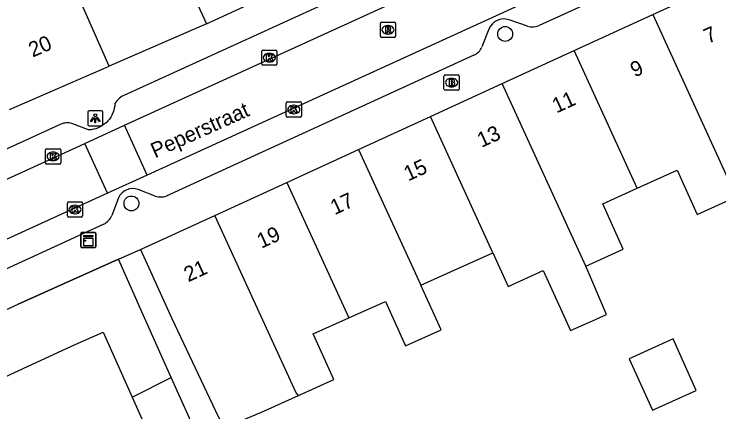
# Model space of a CAD drawing. Extents: x 159888 to 160757, y 384031 to 384746.
# Drawn here: x 160447.04 to 160493.49, y 384427.74 to 384453.93 of the extents above; entities that cross this region are included whole.
import ezdxf

# ---------------------------------------------------------------- set-up
doc = ezdxf.new("R2010")
doc.units = 0
for name, color, linetype in [('IMGEO_Boom', 7, 'Continuous'), ('IMGEO_Brandkraan', 7, 'Continuous'), ('IMGEO_Kast', 7, 'Continuous'), ('IMGEO_Kolk', 7, 'Continuous'), ('IMGEO_Lichtpunt', 7, 'Continuous'), ('IMGEO_Muur', 7, 'Continuous'), ('IMGEO_Openbare_ruimte_label', 7, 'Continuous'), ('IMGEO_Pand', 7, 'Continuous'), ('IMGEO_Pand_nummerreeks', 7, 'Continuous'), ('IMGEO_Rijbaan_lokaal_open', 7, 'Continuous'), ('IMGEO_Rioolput', 7, 'Continuous'), ('IMGEO_Voetpad_open', 7, 'Continuous')]:
    doc.layers.add(name, color=color, linetype=linetype)

msp = doc.modelspace()

# ---------------------------------------------------------------- linework, layer by layer
at = {"layer": 'IMGEO_Boom'}
for centre in [(160479.404, 384452.629), (160454.78, 384441.462)]:
    msp.add_circle(centre, 0.489, dxfattribs=at)
at = {"layer": 'IMGEO_Brandkraan'}
for p, q in [((160475.373, 384448.998), (160475.373, 384449.85)), ((160475.448, 384449.924), (160476.3, 384449.924)), ((160475.861, 384449.704), (160475.886, 384449.704)), ((160476.374, 384449.85), (160476.374, 384448.998)), ((160475.884, 384449.144), (160475.859, 384449.144)), ((160476.3, 384448.924), (160475.448, 384448.924))]:
    msp.add_line(p, q, dxfattribs=at)
for points in [[(160475.373, 384448.998), (160475.373, 384449.85)], [(160475.448, 384449.924), (160476.3, 384449.924)], [(160475.721, 384449.624), (160475.721, 384449.224), (160475.934, 384449.224)], [(160475.952, 384449.624), (160475.721, 384449.624)], [(160475.9, 384449.543), (160475.846, 384449.543), (160475.846, 384449.467)], [(160476.374, 384449.85), (160476.374, 384448.998)], [(160475.846, 384449.467), (160475.899, 384449.467)], [(160475.908, 384449.391), (160475.846, 384449.391), (160475.846, 384449.31)], [(160475.846, 384449.31), (160475.908, 384449.31)], [(160476.3, 384448.924), (160475.448, 384448.924)]]:
    msp.add_lwpolyline(points, dxfattribs=at)
for centre, radius, start, end in [((160475.45, 384449.848), 0.0765, 91.552, 178.448), ((160475.45, 384449.848), 0.0765, 91.552, 178.448), ((160475.901, 384449.505), 0.0379, 267.8285, 90.9355), ((160475.956, 384449.479), 0.145, 59.4692, 91.5367), ((160475.981, 384449.526), 0.0922, 285.5137, 58.1501), ((160476.298, 384449.848), 0.0765, 1.552, 88.448), ((160476.298, 384449.848), 0.0765, 1.552, 88.448), ((160475.909, 384449.35), 0.0404, 269.8759, 90.5077), ((160475.94, 384449.475), 0.251, 268.6676, 293.5347), ((160475.986, 384449.334), 0.105, 301.3115, 78.989), ((160475.45, 384449), 0.0765, 181.552, 268.448), ((160475.45, 384449), 0.0765, 181.552, 268.448), ((160476.298, 384449), 0.0765, 271.552, 358.448), ((160476.298, 384449), 0.0765, 271.552, 358.448)]:
    msp.add_arc(centre, radius, start, end, dxfattribs=at)
for centre, major_axis, ratio, start_param, end_param in [((160475.86, 384449.424), (-0.387, 0.002), 0.722429, 4.712389, 7.853982), ((160475.885, 384449.424), (-0.39, 0.002), 0.717154, 1.570796, 4.712389)]:
    msp.add_ellipse(centre, major_axis=major_axis, ratio=ratio, start_param=start_param, end_param=end_param, dxfattribs=at)
at = {"layer": 'IMGEO_Kast'}
for p, q in [((160451.436, 384438.628), (160451.436, 384439.469)), ((160451.436, 384439.469), (160451.436, 384438.628)), ((160451.511, 384439.553), (160452.352, 384439.553)), ((160452.352, 384439.553), (160451.511, 384439.553)), ((160452.436, 384439.478), (160452.436, 384438.637)), ((160452.436, 384438.637), (160452.436, 384439.478)), ((160452.361, 384438.553), (160451.52, 384438.553)), ((160451.52, 384438.553), (160452.361, 384438.553))]:
    msp.add_line(p, q, dxfattribs=at)
for points in [[(160451.631, 384439.343), (160452.231, 384439.343), (160452.231, 384439.258), (160451.631, 384439.258), (160451.631, 384439.343)], [(160451.631, 384439.168), (160452.231, 384439.168), (160452.231, 384438.679), (160451.631, 384438.679), (160451.631, 384439.168)]]:
    msp.add_lwpolyline(points, dxfattribs=at)
msp.add_circle((160451.715, 384439.017), 0.0377, dxfattribs=at)
for centre, start, end in [((160451.514, 384439.475), 92.4484, 184.2845), ((160451.514, 384439.475), 92.4484, 184.2845), ((160452.358, 384439.475), 2.4484, 94.2845), ((160452.358, 384439.475), 2.4484, 94.2845), ((160451.514, 384438.631), 182.4484, 274.2845), ((160451.514, 384438.631), 182.4484, 274.2845), ((160452.358, 384438.631), 272.4484, 4.2845), ((160452.358, 384438.631), 272.4484, 4.2845)]:
    msp.add_arc(centre, 0.0779, start, end, dxfattribs=at)
at = {"layer": 'IMGEO_Kolk'}
for p, q in [((160463.362, 384450.641), (160463.362, 384451.493)), ((160463.437, 384451.567), (160464.289, 384451.567)), ((160464.363, 384451.493), (160464.363, 384450.641)), ((160463.85, 384451.347), (160463.875, 384451.347)), ((160464.289, 384450.567), (160463.437, 384450.567)), ((160463.873, 384450.787), (160463.848, 384450.787)), ((160465.049, 384448.15), (160465.901, 384448.15)), ((160464.974, 384447.224), (160464.974, 384448.076)), ((160465.462, 384447.93), (160465.487, 384447.93)), ((160465.975, 384448.076), (160465.975, 384447.224)), ((160465.485, 384447.37), (160465.46, 384447.37)), ((160465.901, 384447.15), (160465.049, 384447.15)), ((160449.114, 384444.136), (160449.114, 384444.988)), ((160449.189, 384445.062), (160450.041, 384445.062)), ((160450.115, 384444.988), (160450.115, 384444.136)), ((160449.602, 384444.842), (160449.627, 384444.842)), ((160450.041, 384444.062), (160449.189, 384444.062)), ((160449.625, 384444.282), (160449.6, 384444.282)), ((160450.556, 384440.64), (160450.556, 384441.492)), ((160450.631, 384441.566), (160451.483, 384441.566)), ((160451.044, 384441.346), (160451.069, 384441.346)), ((160451.557, 384441.492), (160451.557, 384440.64)), ((160451.067, 384440.786), (160451.042, 384440.786)), ((160451.483, 384440.566), (160450.631, 384440.566))]:
    msp.add_line(p, q, dxfattribs=at)
for points in [[(160463.362, 384450.641), (160463.362, 384451.493)], [(160463.437, 384451.567), (160464.289, 384451.567)], [(160464.363, 384451.493), (160464.363, 384450.641)], [(160463.683, 384451.267), (160463.806, 384451.267), (160463.806, 384451.116), (160463.936, 384451.267), (160464.1, 384451.267), (160463.954, 384451.116), (160464.107, 384450.867), (160463.955, 384450.867), (160463.87, 384451.031), (160463.806, 384450.964), (160463.806, 384450.867), (160463.683, 384450.867), (160463.683, 384451.267)], [(160464.289, 384450.567), (160463.437, 384450.567)], [(160465.049, 384448.15), (160465.901, 384448.15)], [(160464.974, 384447.224), (160464.974, 384448.076)], [(160465.295, 384447.85), (160465.418, 384447.85), (160465.418, 384447.699), (160465.548, 384447.85), (160465.712, 384447.85), (160465.566, 384447.699), (160465.719, 384447.45), (160465.567, 384447.45), (160465.482, 384447.614), (160465.418, 384447.547), (160465.418, 384447.45), (160465.295, 384447.45), (160465.295, 384447.85)], [(160465.975, 384448.076), (160465.975, 384447.224)], [(160465.901, 384447.15), (160465.049, 384447.15)], [(160449.114, 384444.136), (160449.114, 384444.988)], [(160449.189, 384445.062), (160450.041, 384445.062)], [(160450.115, 384444.988), (160450.115, 384444.136)], [(160449.435, 384444.762), (160449.558, 384444.762), (160449.558, 384444.611), (160449.688, 384444.762), (160449.852, 384444.762), (160449.706, 384444.611), (160449.859, 384444.362), (160449.707, 384444.362), (160449.622, 384444.526), (160449.558, 384444.459), (160449.558, 384444.362), (160449.435, 384444.362), (160449.435, 384444.762)], [(160450.041, 384444.062), (160449.189, 384444.062)], [(160450.556, 384440.64), (160450.556, 384441.492)], [(160450.631, 384441.566), (160451.483, 384441.566)], [(160450.877, 384441.266), (160451, 384441.266), (160451, 384441.115), (160451.13, 384441.266), (160451.294, 384441.266), (160451.148, 384441.115), (160451.301, 384440.866), (160451.149, 384440.866), (160451.064, 384441.03), (160451, 384440.963), (160451, 384440.866), (160450.877, 384440.866), (160450.877, 384441.266)], [(160451.557, 384441.492), (160451.557, 384440.64)], [(160451.483, 384440.566), (160450.631, 384440.566)]]:
    msp.add_lwpolyline(points, dxfattribs=at)
for centre, start, end in [((160463.439, 384451.491), 91.552, 178.448), ((160463.439, 384451.491), 91.552, 178.448), ((160464.287, 384451.491), 1.552, 88.448), ((160464.287, 384451.491), 1.552, 88.448), ((160463.439, 384450.643), 181.552, 268.448), ((160463.439, 384450.643), 181.552, 268.448), ((160464.287, 384450.643), 271.552, 358.448), ((160464.287, 384450.643), 271.552, 358.448), ((160465.051, 384448.074), 91.552, 178.448), ((160465.051, 384448.074), 91.552, 178.448), ((160465.899, 384448.074), 1.552, 88.448), ((160465.899, 384448.074), 1.552, 88.448), ((160465.051, 384447.226), 181.552, 268.448), ((160465.051, 384447.226), 181.552, 268.448), ((160465.899, 384447.226), 271.552, 358.448), ((160465.899, 384447.226), 271.552, 358.448), ((160449.191, 384444.986), 91.552, 178.448), ((160449.191, 384444.986), 91.552, 178.448), ((160450.039, 384444.986), 1.552, 88.448), ((160450.039, 384444.986), 1.552, 88.448), ((160449.191, 384444.138), 181.552, 268.448), ((160449.191, 384444.138), 181.552, 268.448), ((160450.039, 384444.138), 271.552, 358.448), ((160450.039, 384444.138), 271.552, 358.448), ((160450.633, 384441.49), 91.552, 178.448), ((160450.633, 384441.49), 91.552, 178.448), ((160451.481, 384441.49), 1.552, 88.448), ((160451.481, 384441.49), 1.552, 88.448), ((160450.633, 384440.642), 181.552, 268.448), ((160450.633, 384440.642), 181.552, 268.448), ((160451.481, 384440.642), 271.552, 358.448), ((160451.481, 384440.642), 271.552, 358.448)]:
    msp.add_arc(centre, 0.0765, start, end, dxfattribs=at)
for centre, major_axis, ratio, start_param, end_param in [((160463.849, 384451.067), (-0.387, 0.002), 0.722429, 4.712389, 7.853982), ((160463.874, 384451.067), (-0.39, 0.002), 0.717154, 1.570796, 4.712389), ((160465.461, 384447.65), (-0.387, 0.002), 0.722429, 4.712389, 7.853982), ((160465.486, 384447.65), (-0.39, 0.002), 0.717154, 1.570796, 4.712389), ((160449.601, 384444.562), (-0.387, 0.002), 0.722429, 4.712389, 7.853982), ((160449.626, 384444.562), (-0.39, 0.002), 0.717154, 1.570796, 4.712389), ((160451.043, 384441.066), (-0.387, 0.002), 0.722429, 4.712389, 7.853982), ((160451.068, 384441.066), (-0.39, 0.002), 0.717154, 1.570796, 4.712389)]:
    msp.add_ellipse(centre, major_axis=major_axis, ratio=ratio, start_param=start_param, end_param=end_param, dxfattribs=at)
at = {"layer": 'IMGEO_Lichtpunt'}
for p, q in [((160451.894, 384447.474), (160451.894, 384446.667)), ((160451.894, 384447.474), (160451.894, 384446.667)), ((160452.796, 384447.569), (160451.988, 384447.569)), ((160452.796, 384447.569), (160451.988, 384447.569)), ((160452.89, 384446.667), (160452.89, 384447.474)), ((160452.89, 384446.667), (160452.89, 384447.474)), ((160451.988, 384446.573), (160452.796, 384446.573)), ((160451.988, 384446.573), (160452.796, 384446.573))]:
    msp.add_line(p, q, dxfattribs=at)
for points in [[(160452.268, 384447.138), (160452.307, 384447.11), (160452.119, 384446.848), (160452.081, 384446.875), (160452.268, 384447.138)], [(160452.37, 384447.09), (160452.417, 384447.09), (160452.417, 384446.768), (160452.37, 384446.768), (160452.37, 384447.09)], [(160452.48, 384447.11), (160452.518, 384447.137), (160452.705, 384446.875), (160452.666, 384446.847), (160452.48, 384447.11)]]:
    msp.add_lwpolyline(points, dxfattribs=at)
msp.add_circle((160452.393, 384447.272), 0.0994, dxfattribs=at)
for centre, start, end in [((160451.988, 384447.474), 90, 180), ((160451.988, 384447.474), 90, 180), ((160452.796, 384447.474), 0, 90), ((160452.796, 384447.474), 0, 90), ((160451.988, 384446.667), 180, 270), ((160451.988, 384446.667), 180, 270), ((160452.796, 384446.667), 270, 0), ((160452.796, 384446.667), 270, 360)]:
    msp.add_arc(centre, 0.0946, start, end, dxfattribs=at)
at = {"layer": 'IMGEO_Muur'}
msp.add_lwpolyline([(160453.931, 384437.792), (160447.309, 384434.839)], dxfattribs=at)
at = {"layer": 'IMGEO_Pand'}
for points in [[(160454.088, 384465.492), (160459.727, 384453.302)], [(160453.303, 384450.51), (160450.11, 384457.763)], [(160489.138, 384453.904), (160494.567, 384456.391)], [(160459.727, 384453.302), (160465.459, 384455.957)], [(160483.95, 384451.527), (160489.138, 384453.904)], [(160489.138, 384453.904), (160494.635, 384441.9)], [(160459.727, 384453.302), (160453.303, 384450.51)], [(160479.215, 384449.358), (160483.95, 384451.527)], [(160488.096, 384442.47), (160483.95, 384451.527)], [(160446.743, 384447.659), (160453.303, 384450.51)], [(160474.48, 384447.188), (160479.215, 384449.358)], [(160484.717, 384437.341), (160479.215, 384449.358)], [(160469.745, 384445.019), (160474.48, 384447.188)], [(160478.586, 384438.22), (160474.48, 384447.188)], [(160465.01, 384442.85), (160469.745, 384445.019)], [(160469.745, 384445.019), (160473.839, 384436.077)], [(160488.096, 384442.47), (160490.734, 384443.661), (160492.055, 384440.736), (160494.635, 384441.9)], [(160460.276, 384440.681), (160465.01, 384442.85)], [(160465.01, 384442.85), (160469.101, 384433.926)], [(160484.717, 384437.341), (160487.184, 384438.455), (160485.833, 384441.449), (160488.096, 384442.47)], [(160455.382, 384438.439), (160460.276, 384440.681)], [(160465.784, 384428.812), (160465.625, 384428.999), (160460.276, 384440.681)], [(160455.382, 384438.439), (160457.439, 384433.882), (160460.493, 384427.436), (160460.892, 384426.684)], [(160473.839, 384436.077), (160476.242, 384437.162), (160478.586, 384438.22)], [(160478.586, 384438.22), (160479.61, 384435.984), (160481.915, 384437.039), (160482.255, 384436.285), (160483.699, 384433.086), (160484.959, 384433.655), (160486.076, 384434.16), (160484.717, 384437.341)], [(160433.519, 384424.249), (160433.504, 384425.741), (160439.345, 384431.166), (160447.309, 384434.839), (160453.93, 384437.792)], [(160457.405, 384430.008), (160455.56, 384434.139), (160453.93, 384437.792)], [(160469.101, 384433.926), (160471.51, 384435.014), (160472.834, 384432.082), (160475.183, 384433.142), (160473.839, 384436.077)], [(160465.784, 384428.812), (160468.114, 384429.864), (160466.757, 384432.868), (160469.101, 384433.926)], [(160442.579, 384427.165), (160444.334, 384428.795), (160444.591, 384429.182), (160448.254, 384430.872), (160451.074, 384432.172), (160452.913, 384432.978), (160454.815, 384428.715)], [(160489.106, 384427.843), (160491.997, 384429.146), (160490.466, 384432.541), (160487.575, 384431.238), (160489.106, 384427.843)], [(160454.815, 384428.715), (160457.405, 384430.008)], [(160459.209, 384425.964), (160457.405, 384430.008)], [(160454.815, 384428.715), (160457.121, 384423.549), (160459.411, 384425.511), (160459.209, 384425.964)], [(160460.892, 384426.684), (160463.343, 384427.71), (160465.784, 384428.812)]]:
    msp.add_lwpolyline(points, dxfattribs=at)
at = {"layer": 'IMGEO_Rijbaan_lokaal_open'}
for points in [[(160454.317, 384446.611), (160493.72, 384464.601)], [(160495.213, 384461.332), (160455.807, 384443.337)], [(160451.715, 384445.423), (160454.317, 384446.611)], [(160455.807, 384443.337), (160454.317, 384446.611)], [(160427.031, 384432.494), (160428.207, 384433.465), (160429.629, 384434.635), (160431.79, 384436.112), (160434.074, 384437.389), (160447.578, 384443.534), (160451.715, 384445.423)], [(160453.206, 384442.149), (160451.715, 384445.423)], [(160455.807, 384443.337), (160453.206, 384442.149)], [(160453.206, 384442.149), (160435.156, 384433.906), (160430.297, 384430.523), (160430.292, 384430.519)]]:
    msp.add_lwpolyline(points, dxfattribs=at)
at = {"layer": 'IMGEO_Rioolput'}
for p, q in [((160471.182, 384452.476), (160471.182, 384453.328)), ((160471.257, 384453.402), (160472.109, 384453.402)), ((160472.183, 384453.328), (160472.183, 384452.476)), ((160471.67, 384453.182), (160471.695, 384453.182)), ((160472.109, 384452.402), (160471.257, 384452.402)), ((160471.693, 384452.622), (160471.668, 384452.622))]:
    msp.add_line(p, q, dxfattribs=at)
for points in [[(160471.182, 384452.476), (160471.182, 384453.328)], [(160471.257, 384453.402), (160472.109, 384453.402)], [(160472.183, 384453.328), (160472.183, 384452.476)], [(160471.771, 384453.1), (160471.519, 384453.102), (160471.519, 384452.702)], [(160471.519, 384452.702), (160471.643, 384452.702), (160471.643, 384452.864), (160471.654, 384452.864)], [(160471.697, 384453.021), (160471.643, 384453.021), (160471.643, 384452.94)], [(160471.643, 384452.94), (160471.695, 384452.94)], [(160471.701, 384452.835), (160471.772, 384452.702), (160471.912, 384452.702), (160471.847, 384452.828)], [(160472.109, 384452.402), (160471.257, 384452.402)]]:
    msp.add_lwpolyline(points, dxfattribs=at)
for centre, radius, start, end in [((160471.259, 384453.326), 0.0765, 91.552, 178.448), ((160471.259, 384453.326), 0.0765, 91.552, 178.448), ((160472.107, 384453.326), 0.0765, 1.552, 88.448), ((160472.107, 384453.326), 0.0765, 1.552, 88.448), ((160471.653, 384452.811), 0.0533, 26.0293, 88.6989), ((160471.679, 384453.129), 0.19, 274.7715, 282.9687), ((160471.703, 384452.925), 0.0964, 77.0061, 93.1865), ((160471.717, 384452.982), 0.0378, 276.6634, 79.6772), ((160471.77, 384452.99), 0.109, 350.3612, 89.416), ((160471.768, 384452.99), 0.112, 277.5842, 350.9817), ((160471.752, 384452.775), 0.108, 29.5134, 73.7905), ((160471.259, 384452.478), 0.0765, 181.552, 268.448), ((160471.259, 384452.478), 0.0765, 181.552, 268.448), ((160472.107, 384452.478), 0.0765, 271.552, 358.448), ((160472.107, 384452.478), 0.0765, 271.552, 358.448)]:
    msp.add_arc(centre, radius, start, end, dxfattribs=at)
for centre, major_axis, ratio, start_param, end_param in [((160471.669, 384452.902), (-0.387, 0.002), 0.722429, 4.712389, 7.853982), ((160471.694, 384452.902), (-0.39, 0.002), 0.717154, 1.570796, 4.712389)]:
    msp.add_ellipse(centre, major_axis=major_axis, ratio=ratio, start_param=start_param, end_param=end_param, dxfattribs=at)
at = {"layer": 'IMGEO_Voetpad_open'}
for points in [[(160495.357, 384459.421), (160481.641, 384453.176)], [(160474.316, 384457.729), (160454.273, 384448.571), (160454.171, 384448.52), (160454.074, 384448.46), (160453.982, 384448.391), (160453.897, 384448.314), (160453.819, 384448.231), (160453.75, 384448.14), (160453.684, 384448.037), (160453.674, 384447.896), (160453.65, 384447.739), (160453.611, 384447.584), (160453.559, 384447.434), (160453.493, 384447.288), (160453.415, 384447.15), (160453.325, 384447.018), (160453.224, 384446.896), (160453.111, 384446.782), (160452.99, 384446.68), (160452.859, 384446.588), (160452.721, 384446.509), (160452.576, 384446.442), (160452.426, 384446.389), (160452.272, 384446.349), (160452.115, 384446.323), (160451.956, 384446.311), (160450.857, 384446.732), (160450.765, 384446.755), (160450.672, 384446.769), (160450.578, 384446.775), (160450.483, 384446.773), (160450.39, 384446.762), (160450.297, 384446.743), (160450.207, 384446.715), (160450.119, 384446.68), (160450.082, 384446.662), (160433.681, 384439.158)], [(160480.886, 384453.138), (160479.659, 384453.561)], [(160478.336, 384452.953), (160477.874, 384451.768)], [(160477.338, 384451.227), (160457.075, 384441.954)], [(160456.348, 384441.951), (160455.22, 384442.392)], [(160453.922, 384441.83), (160453.492, 384440.662)], [(160452.963, 384440.089), (160437.486, 384433.018)], [(160453.93, 384437.792), (160455.382, 384438.439)]]:
    msp.add_lwpolyline(points, dxfattribs=at)
for centre, radius, start, end in [((160479.326, 384452.542), 1.072, 71.8906, 157.4728), ((160481.213, 384454.155), 1.068, 252.1644, 293.5983), ((160476.942, 384452.155), 1.009, 293.0966, 337.4354), ((160454.882, 384441.393), 1.054, 71.2908, 155.5319), ((160456.707, 384442.978), 1.088, 250.7241, 289.7488), ((160452.15, 384441.37), 1.517, 302.3959, 332.177)]:
    msp.add_arc(centre, radius, start, end, dxfattribs=at)

# ---------------------------------------------------------------- texts
at = {"layer": 'IMGEO_Openbare_ruimte_label'}
msp.add_text('Peperstraat', height=1, rotation=24.2068, dxfattribs=at).set_placement((160456.33, 384444.434))
at = {"layer": 'IMGEO_Pand_nummerreeks'}
for s, rotation, p in [('7', 24.6143, (160492.775, 384451.963)), ('20', 23.4913, (160448.264, 384451.067)), ('9', 24.6142, (160487.938, 384449.747)), ('11', 24.6142, (160482.787, 384447.387)), ('13', 24.6143, (160477.846, 384445.123)), ('15', 24.6143, (160473.009, 384442.907)), ('17', 24.6143, (160468.172, 384440.691)), ('19', 24.6142, (160463.335, 384438.476)), ('21', 24.6143, (160458.518, 384436.268))]:
    msp.add_text(s, height=1, rotation=rotation, dxfattribs=at).set_placement(p)

doc.saveas('drawing.dxf')
